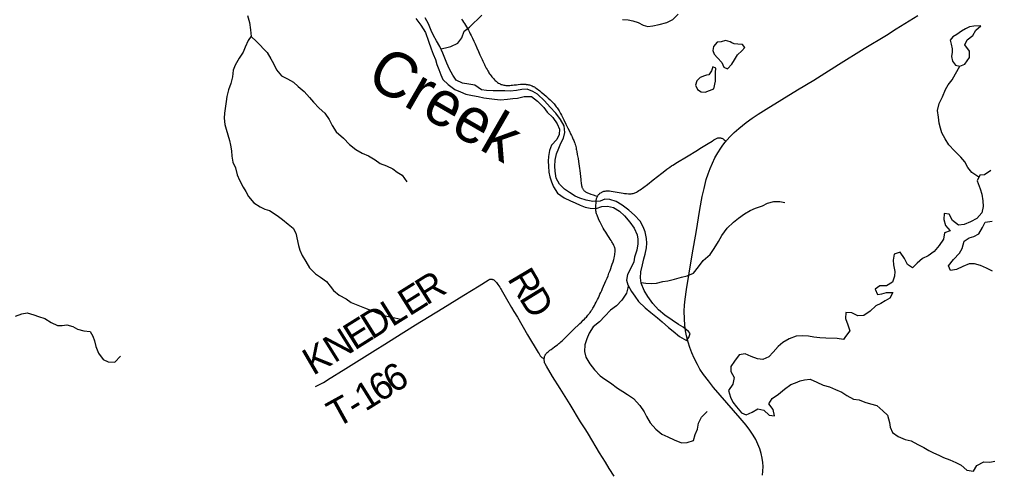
# Model space of a CAD drawing. Extents: x 1442749 to 1756758, y 235267 to 677782.
# Drawn here: x 1557967 to 1568709, y 507542 to 512566 of the extents above; entities that cross this region are included whole.
import ezdxf

# ---------------------------------------------------------------- set-up
doc = ezdxf.new("R2010")
doc.units = 0
for name, color, linetype in [('GM_X_Major_Lake', 7, 'Continuous'), ('GM_X_Major_River', 7, 'Continuous'), ('GM_X_Major_River_Text', 7, 'Continuous'), ('GM_X_Minor_Lake', 7, 'Continuous'), ('GM_X_Minor_River', 7, 'Continuous'), ('GM_X_State_Route', 7, 'Continuous'), ('GM_X_Township_Road', 7, 'Continuous'), ('GM_X_Township_Road_Text', 7, 'Continuous')]:
    doc.layers.add(name, color=color, linetype=linetype)

msp = doc.modelspace()

# ---------------------------------------------------------------- linework, layer by layer
at = {"layer": 'GM_X_Major_Lake'}
for points in [[(1568713, 510894), (1568643, 510848), (1568591, 510845), (1568560, 510782), (1568595, 510693), (1568613, 510634), (1568623, 510558), (1568629, 510495), (1568613, 510426), (1568556, 510365), (1568489, 510329), (1568418, 510299), (1568355, 510289), (1568287, 510343), (1568253, 510412), (1568195, 510419), (1568193, 510353), (1568211, 510287), (1568264, 510229)], [(1568729, 509782), (1568666, 509813), (1568599, 509843), (1568533, 509861), (1568471, 509863), (1568402, 509833), (1568331, 509801), (1568267, 509788), (1568245, 509841), (1568301, 509910), (1568365, 509982), (1568396, 510033), (1568418, 510113), (1568471, 510151), (1568526, 510166), (1568579, 510196), (1568621, 510263), (1568648, 510325), (1568727, 510336)], [(1568264, 510229), (1568201, 510205), (1568187, 510137), (1568141, 510066), (1568085, 510000), (1568020, 509951), (1567957, 509923), (1567899, 509871), (1567846, 509818), (1567789, 509854), (1567757, 509921), (1567711, 509990), (1567644, 509970), (1567632, 509902), (1567635, 509850), (1567649, 509779), (1567647, 509725), (1567623, 509658), (1567558, 509620), (1567486, 509618), (1567433, 509581), (1567457, 509524), (1567508, 509531), (1567558, 509544), (1567628, 509546), (1567596, 509484), (1567545, 509452), (1567495, 509423), (1567440, 509397), (1567376, 509340), (1567309, 509292), (1567241, 509286), (1567174, 509320), (1567110, 509324), (1567106, 509258), (1567130, 509189), (1567152, 509122), (1567104, 509057)], [(1567104, 509057), (1567081, 509024), (1567014, 509038), (1566888, 509041), (1566820, 509045), (1566754, 509051), (1566694, 509063), (1566632, 509066), (1566558, 509064), (1566483, 509034), (1566412, 508994), (1566359, 508948), (1566303, 508885), (1566258, 508834), (1566191, 508806), (1566131, 508812), (1566062, 508838), (1565995, 508868), (1565930, 508856), (1565876, 508787), (1565835, 508728), (1565837, 508672), (1565873, 508605), (1565857, 508531), (1565811, 508460), (1565831, 508386), (1565859, 508333), (1565898, 508282), (1565954, 508216), (1566007, 508194), (1566072, 508223), (1566135, 508257), (1566203, 508243), (1566259, 508187), (1566319, 508182), (1566303, 508250), (1566255, 508314), (1566292, 508373), (1566364, 508421), (1566429, 508475), (1566499, 508529), (1566551, 508548), (1566602, 508568), (1566652, 508581), (1566715, 508585), (1566786, 508553), (1566857, 508519), (1566926, 508503), (1566993, 508472), (1567064, 508442), (1567121, 508406), (1567192, 508366), (1567256, 508358), (1567317, 508332), (1567383, 508313), (1567450, 508295), (1567517, 508235), (1567569, 508187), (1567591, 508108), (1567599, 508056), (1567624, 507995), (1567688, 507954), (1567765, 507919), (1567831, 507903), (1567904, 507863), (1567971, 507830), (1568026, 507798), (1568079, 507772), (1568137, 507745), (1568188, 507719), (1568259, 507693), (1568324, 507665), (1568385, 507636), (1568448, 507580), (1568519, 507568), (1568559, 507633), (1568634, 507671), (1568702, 507669), (1568755, 507680)]]:
    msp.add_lwpolyline(points, dxfattribs=at)
at = {"layer": 'GM_X_Major_River'}
for points in [[(1562353, 512578), (1562409, 512504), (1562458, 512423), (1562491, 512326), (1562521, 512241), (1562543, 512182), (1562568, 512123), (1562586, 512069), (1562607, 512014), (1562627, 511953), (1562651, 511901), (1562708, 511845), (1562784, 511791), (1562845, 511765), (1562905, 511741), (1562980, 511725), (1563040, 511712), (1563103, 511698), (1563163, 511692), (1563221, 511683), (1563289, 511677), (1563365, 511683), (1563425, 511691), (1563477, 511696), (1563550, 511714), (1563632, 511715), (1563699, 511663), (1563767, 511593), (1563803, 511542), (1563869, 511480), (1563917, 511413), (1563940, 511354), (1563936, 511292), (1563910, 511239), (1563853, 511174), (1563829, 511117), (1563819, 511049), (1563817, 510997)], [(1563464, 511780), (1563396, 511774), (1563336, 511778), (1563266, 511778), (1563206, 511775), (1563132, 511779), (1563078, 511789), (1563004, 511839), (1562940, 511849), (1562870, 511861), (1562797, 511895), (1562761, 511950), (1562723, 512015), (1562695, 512084), (1562674, 512136), (1562652, 512193), (1562616, 512266), (1562580, 512331), (1562549, 512388), (1562523, 512445), (1562493, 512516), (1562455, 512583)], [(1565368, 509115), (1565309, 509161), (1565258, 509193), (1565187, 509241), (1565107, 509295), (1565038, 509353), (1564974, 509425), (1564919, 509500), (1564879, 509568), (1564845, 509647), (1564837, 509709), (1564842, 509773), (1564859, 509851), (1564875, 509918), (1564888, 509970), (1564902, 510038), (1564908, 510090), (1564903, 510144), (1564887, 510218), (1564865, 510271), (1564835, 510336), (1564770, 510402), (1564708, 510458), (1564636, 510510), (1564567, 510552), (1564497, 510574), (1564441, 510577), (1564391, 510557), (1564309, 510551), (1564237, 510567), (1564166, 510589), (1564114, 510612), (1564052, 510652), (1563997, 510690), (1563940, 510745), (1563904, 510810), (1563892, 510887), (1563888, 510943), (1563892, 511011), (1563908, 511081), (1563932, 511142), (1563957, 511196), (1563985, 511251), (1563999, 511315), (1563991, 511389), (1563951, 511458), (1563899, 511530), (1563839, 511597), (1563775, 511667), (1563699, 511738), (1563648, 511769), (1563582, 511795), (1563526, 511790), (1563464, 511780)], [(1563817, 510997), (1563818, 510943), (1563824, 510877), (1563835, 510824), (1563851, 510770), (1563875, 510713), (1563919, 510644), (1563994, 510592), (1564061, 510558), (1564114, 510536), (1564170, 510513), (1564225, 510491), (1564279, 510478), (1564345, 510476), (1564409, 510498), (1564473, 510502), (1564537, 510484), (1564604, 510445), (1564660, 510393), (1564718, 510323), (1564766, 510256), (1564800, 510185), (1564809, 510134), (1564809, 510082), (1564795, 510013), (1564771, 509937), (1564764, 509883), (1564725, 509808), (1564692, 509745), (1564684, 509681), (1564698, 509629), (1564738, 509557), (1564775, 509504), (1564815, 509445), (1564889, 509375), (1564952, 509325), (1565024, 509265), (1565075, 509220), (1565145, 509158), (1565200, 509118), (1565270, 509058), (1565345, 509016)], [(1565345, 509016), (1565370, 509048), (1565387, 509093), (1565368, 509115)]]:
    msp.add_lwpolyline(points, dxfattribs=at)
at = {"layer": 'GM_X_Minor_Lake'}
for points in [[(1568523, 512490), (1568475, 512483), (1568431, 512462), (1568386, 512436), (1568336, 512401), (1568293, 512372), (1568264, 512337), (1568275, 512294), (1568286, 512242), (1568286, 512204), (1568279, 512158), (1568290, 512106), (1568323, 512059), (1568368, 512050)], [(1568368, 512050), (1568423, 512073), (1568476, 512144), (1568476, 512214), (1568425, 512287), (1568452, 512341), (1568515, 512390), (1568547, 512449), (1568600, 512494), (1568523, 512490)], [(1565847, 512309), (1565829, 512317), (1565778, 512332), (1565729, 512319), (1565685, 512313), (1565644, 512268), (1565638, 512224), (1565651, 512182), (1565688, 512143)], [(1565688, 512143), (1565735, 512088), (1565760, 512040), (1565801, 512021), (1565846, 512072), (1565877, 512119), (1565911, 512173), (1565957, 512220), (1565990, 512257), (1565965, 512290), (1565915, 512291), (1565873, 512298), (1565847, 512309)], [(1565647, 511800), (1565665, 511883), (1565667, 511979), (1565671, 512027), (1565638, 512042), (1565623, 511996), (1565594, 511955), (1565566, 511948)], [(1565566, 511948), (1565546, 511944), (1565497, 511925), (1565461, 511887), (1565444, 511839), (1565467, 511791), (1565508, 511766), (1565554, 511763), (1565647, 511800)]]:
    msp.add_lwpolyline(points, dxfattribs=at)
at = {"layer": 'GM_X_Minor_River'}
for points in [[(1564638, 512567), (1564702, 512563), (1564754, 512552), (1564810, 512533), (1564865, 512502), (1564917, 512487), (1564975, 512496), (1565045, 512512), (1565128, 512533), (1565194, 512564), (1565254, 512624)], [(1560491, 512608), (1560513, 512532), (1560525, 512453), (1560532, 512377), (1560591, 512322), (1560706, 512201), (1560749, 512130), (1560778, 512078), (1560812, 512009), (1560867, 511942), (1560934, 511908), (1561000, 511871), (1561051, 511826), (1561116, 511770), (1561174, 511703), (1561219, 511652), (1561284, 511585), (1561345, 511530), (1561395, 511461), (1561428, 511394), (1561470, 511323), (1561553, 511251), (1561618, 511184), (1561688, 511126), (1561758, 511087), (1561829, 511059), (1561904, 511012), (1561959, 510973), (1562029, 510945), (1562096, 510912), (1562147, 510877), (1562201, 510842), (1562251, 510771)], [(1562628, 512241), (1562682, 512253), (1562740, 512265), (1562815, 512302), (1562860, 512361), (1562887, 512435), (1562944, 512482), (1563081, 512613)], [(1560532, 512381), (1560497, 512332), (1560463, 512260), (1560442, 512204), (1560399, 512137), (1560355, 512060), (1560330, 512006), (1560325, 511932), (1560307, 511857), (1560280, 511787), (1560262, 511715), (1560253, 511657), (1560236, 511531), (1560233, 511475), (1560240, 511405), (1560255, 511353), (1560274, 511290), (1560290, 511226), (1560301, 511176), (1560312, 511111), (1560317, 511055), (1560329, 510989), (1560356, 510924), (1560376, 510848), (1560403, 510787), (1560442, 510712), (1560471, 510661), (1560502, 510609), (1560560, 510537), (1560631, 510492), (1560683, 510467), (1560734, 510454), (1560817, 510396), (1560876, 510353), (1560941, 510302), (1560994, 510258), (1561023, 510202), (1561053, 510065), (1561069, 510015), (1561096, 509954), (1561137, 509889), (1561174, 509820), (1561242, 509751), (1561297, 509716), (1561364, 509668), (1561405, 509617), (1561440, 509567), (1561503, 509517), (1561582, 509474), (1561638, 509436), (1561709, 509405), (1561784, 509376), (1561852, 509350), (1561919, 509321), (1561997, 509291), (1562100, 509269), (1562172, 509254)], [(1568580, 510823), (1568502, 510874), (1568457, 510927), (1568423, 510991), (1568380, 511044), (1568311, 511112), (1568248, 511179), (1568208, 511246), (1568171, 511313), (1568154, 511365), (1568141, 511420), (1568133, 511486), (1568124, 511560), (1568142, 511636), (1568177, 511711), (1568211, 511791), (1568242, 511844), (1568285, 511897), (1568323, 511965), (1568368, 512050)], [(1564844, 509656), (1564895, 509647), (1564964, 509645), (1565015, 509650), (1565085, 509667), (1565139, 509676), (1565213, 509693), (1565292, 509715), (1565354, 509730), (1565425, 509759), (1565478, 509830), (1565530, 509899), (1565607, 509967), (1565653, 510034), (1565700, 510110), (1565738, 510177), (1565797, 510258), (1565865, 510325), (1565921, 510368), (1565986, 510414), (1566049, 510453), (1566108, 510480), (1566188, 510505), (1566243, 510534), (1566311, 510552), (1566379, 510551), (1566433, 510542)], [(1564702, 509621), (1564697, 509596), (1564684, 509537), (1564631, 509462), (1564573, 509397), (1564506, 509350), (1564443, 509285), (1564382, 509222), (1564315, 509165), (1564269, 509096), (1564242, 509033), (1564222, 508965), (1564219, 508893), (1564232, 508829), (1564278, 508756), (1564327, 508690), (1564391, 508625), (1564443, 508588), (1564506, 508545), (1564583, 508487), (1564640, 508450), (1564693, 508417), (1564758, 508373), (1564829, 508296), (1564879, 508227), (1564904, 508172), (1564945, 508105), (1565007, 508032), (1565072, 507977), (1565140, 507947), (1565211, 507914), (1565292, 507884), (1565354, 507887), (1565423, 507910), (1565442, 507975), (1565467, 508033), (1565479, 508099), (1565512, 508168), (1565576, 508229)], [(1557922, 509283), (1557993, 509310), (1558053, 509321), (1558126, 509299), (1558180, 509280), (1558248, 509257), (1558319, 509213), (1558388, 509182), (1558440, 509179), (1558492, 509186), (1558558, 509169), (1558611, 509139), (1558681, 509120), (1558749, 509115), (1558780, 509064), (1558797, 509012), (1558811, 508947), (1558842, 508873), (1558892, 508803), (1558948, 508778), (1559024, 508775), (1559085, 508842)]]:
    msp.add_lwpolyline(points, dxfattribs=at)
at = {"layer": 'GM_X_State_Route'}
msp.add_lwpolyline([(1566188, 507526), (1566192, 507569), (1566193, 507619), (1566190, 507665), (1566183, 507714), (1566172, 507766), (1566157, 507817), (1566136, 507869), (1566112, 507919), (1566084, 507968), (1566048, 508023), (1566006, 508079), (1565941, 508157), (1565645, 508495), (1565623, 508523), (1565588, 508567), (1565533, 508640), (1565495, 508697), (1565466, 508748), (1565430, 508818), (1565404, 508878), (1565393, 508907), (1565382, 508936), (1565364, 508995), (1565346, 509065), (1565335, 509123), (1565327, 509184), (1565323, 509253), (1565321, 509338), (1565324, 509406), (1565330, 509471), (1565345, 509578), (1565375, 509760), (1565414, 509986), (1565452, 510209), (1565494, 510465), (1565521, 510606), (1565540, 510696), (1565565, 510794), (1565584, 510857), (1565606, 510918), (1565632, 510978), (1565661, 511037), (1565692, 511091), (1565724, 511143), (1565747, 511176), (1565774, 511210), (1565783, 511221), (1565788, 511227), (1565795, 511234), (1565824, 511266), (1565872, 511315), (1565923, 511361), (1566005, 511427), (1566074, 511475), (1566140, 511518), (1566226, 511573), (1566572, 511786), (1566754, 511896), (1566835, 511947), (1567029, 512069), (1567311, 512243), (1567558, 512393), (1567666, 512461), (1567906, 512610)], dxfattribs=at)
at = {"layer": 'GM_X_Township_Road'}
for points in [[(1562857, 512569), (1562869, 512553), (1562880, 512537), (1562890, 512522), (1562901, 512504), (1562911, 512486), (1562923, 512465), (1562933, 512448), (1562944, 512427), (1562954, 512408), (1562964, 512387), (1562978, 512358), (1562993, 512327), (1563008, 512295), (1563027, 512252), (1563044, 512213), (1563060, 512176), (1563074, 512144), (1563084, 512124), (1563094, 512104), (1563103, 512083), (1563111, 512068), (1563117, 512055), (1563124, 512041), (1563131, 512028), (1563140, 512014), (1563148, 511999), (1563155, 511988), (1563161, 511977), (1563168, 511966), (1563175, 511956), (1563184, 511943), (1563194, 511930), (1563203, 511919), (1563213, 511908), (1563221, 511899), (1563229, 511891), (1563239, 511882), (1563248, 511875), (1563257, 511868), (1563267, 511862), (1563276, 511857), (1563286, 511852), (1563294, 511848), (1563304, 511845), (1563314, 511842), (1563325, 511839), (1563335, 511838), (1563346, 511836), (1563360, 511835), (1563373, 511836), (1563390, 511836), (1563407, 511838), (1563421, 511839), (1563441, 511841), (1563464, 511844), (1563485, 511847), (1563508, 511849), (1563524, 511850), (1563539, 511850), (1563548, 511850), (1563557, 511850), (1563567, 511849), (1563574, 511848), (1563582, 511847), (1563591, 511845), (1563600, 511844), (1563610, 511841), (1563619, 511838), (1563629, 511835), (1563637, 511831), (1563649, 511826), (1563655, 511823), (1563663, 511819), (1563672, 511814), (1563684, 511806), (1563698, 511796), (1563710, 511787), (1563722, 511778), (1563739, 511763), (1563753, 511752), (1563769, 511738), (1563798, 511712), (1563817, 511694), (1563838, 511675), (1563852, 511662), (1563862, 511652), (1563874, 511640), (1563882, 511631), (1563890, 511621), (1563898, 511612), (1563906, 511601), (1563915, 511589), (1563923, 511577), (1563930, 511566), (1563937, 511555), (1563944, 511542), (1563952, 511527), (1563962, 511509), (1563971, 511491), (1563989, 511454), (1564013, 511406), (1564034, 511364), (1564050, 511331), (1564064, 511301), (1564073, 511283), (1564080, 511269), (1564085, 511258), (1564090, 511247), (1564094, 511238), (1564098, 511228), (1564102, 511217), (1564107, 511205), (1564110, 511196), (1564113, 511184), (1564117, 511174), (1564120, 511160), (1564124, 511146), (1564127, 511132), (1564130, 511120), (1564133, 511104), (1564138, 511072), (1564146, 511026), (1564152, 510994), (1564156, 510968), (1564160, 510943), (1564164, 510917), (1564167, 510894), (1564170, 510861), (1564173, 510829), (1564176, 510796), (1564178, 510776), (1564179, 510762), (1564181, 510749), (1564183, 510739), (1564185, 510728), (1564187, 510718), (1564190, 510710), (1564192, 510703), (1564195, 510698), (1564198, 510692), (1564202, 510686), (1564207, 510680), (1564211, 510675), (1564215, 510670), (1564222, 510666), (1564230, 510660), (1564237, 510656), (1564244, 510652), (1564252, 510648), (1564262, 510644), (1564287, 510634), (1564314, 510625), (1564344, 510615), (1564361, 510609)], [(1564361, 510609), (1564366, 510616), (1564370, 510622), (1564374, 510628), (1564379, 510633), (1564384, 510638), (1564389, 510643), (1564397, 510649), (1564404, 510653), (1564411, 510657), (1564418, 510660), (1564425, 510663), (1564431, 510665), (1564438, 510666), (1564448, 510668), (1564458, 510669), (1564468, 510670), (1564479, 510670), (1564494, 510669), (1564513, 510667), (1564601, 510652), (1564644, 510645), (1564660, 510642), (1564684, 510639), (1564704, 510637), (1564716, 510636), (1564724, 510636), (1564733, 510637), (1564745, 510639), (1564755, 510642), (1564766, 510645), (1564774, 510648), (1564785, 510652), (1564793, 510657), (1564805, 510664), (1564819, 510672), (1564832, 510680), (1564848, 510691), (1564861, 510700), (1564875, 510710), (1564915, 510741), (1564977, 510790), (1565024, 510827), (1565074, 510867), (1565106, 510891), (1565128, 510908), (1565149, 510923), (1565163, 510933), (1565181, 510945), (1565195, 510954), (1565212, 510965), (1565229, 510975), (1565363, 511056), (1565448, 511109), (1565513, 511149), (1565586, 511194), (1565630, 511221), (1565649, 511234), (1565662, 511241), (1565671, 511246), (1565679, 511250), (1565685, 511252), (1565693, 511255), (1565700, 511256), (1565708, 511257), (1565713, 511257), (1565718, 511257), (1565723, 511256), (1565730, 511254), (1565736, 511252), (1565744, 511249), (1565750, 511246), (1565756, 511242), (1565764, 511236), (1565774, 511228), (1565783, 511221)], [(1563772, 508814), (1563774, 508826), (1563774, 508831), (1563776, 508838), (1563778, 508844), (1563781, 508850), (1563784, 508856), (1563787, 508860), (1563790, 508865), (1563794, 508869), (1563799, 508875), (1563805, 508881), (1563814, 508889), (1563823, 508897), (1563834, 508906), (1563848, 508916), (1563866, 508929), (1563886, 508943), (1563901, 508954), (1563920, 508968), (1563935, 508980), (1563946, 508989), (1563957, 508998), (1563969, 509009), (1563983, 509022), (1563997, 509035), (1564012, 509050), (1564031, 509068), (1564057, 509096), (1564111, 509150), (1564147, 509185), (1564166, 509202), (1564183, 509219), (1564203, 509238), (1564218, 509252), (1564230, 509264), (1564238, 509273), (1564246, 509283), (1564256, 509294), (1564264, 509304), (1564271, 509313), (1564280, 509326), (1564286, 509334), (1564293, 509345), (1564301, 509358), (1564309, 509371), (1564317, 509384), (1564327, 509403), (1564337, 509421), (1564346, 509438), (1564360, 509467), (1564371, 509488), (1564379, 509506), (1564389, 509527), (1564399, 509547), (1564408, 509568), (1564418, 509590), (1564429, 509616), (1564444, 509650), (1564455, 509676), (1564467, 509705), (1564478, 509731), (1564488, 509758), (1564500, 509790), (1564508, 509812), (1564517, 509837), (1564525, 509860), (1564534, 509886), (1564541, 509910), (1564546, 509927), (1564551, 509949), (1564554, 509962), (1564555, 509974), (1564557, 509997), (1564558, 510010), (1564557, 510019), (1564557, 510027), (1564555, 510035), (1564553, 510041), (1564550, 510050), (1564546, 510059), (1564542, 510067), (1564537, 510077), (1564532, 510086), (1564527, 510095), (1564520, 510106), (1564511, 510122), (1564501, 510136), (1564489, 510155), (1564476, 510176), (1564452, 510214), (1564437, 510238), (1564425, 510258), (1564414, 510278), (1564402, 510301), (1564390, 510324), (1564378, 510349), (1564368, 510371), (1564360, 510389), (1564356, 510402), (1564351, 510416), (1564347, 510428), (1564345, 510438), (1564343, 510449), (1564342, 510462), (1564342, 510475), (1564342, 510490), (1564343, 510505), (1564345, 510541), (1564347, 510556), (1564348, 510569), (1564350, 510579), (1564352, 510587), (1564354, 510593), (1564357, 510601), (1564361, 510609)], [(1561244, 508507), (1561300, 508534), (1561317, 508543), (1561331, 508551), (1561349, 508561), (1561376, 508578), (1561577, 508703), (1561814, 508852), (1561903, 508908), (1562008, 508974), (1562120, 509043), (1562350, 509188), (1562649, 509372), (1562884, 509516), (1563052, 509618), (1563151, 509681), (1563157, 509685), (1563161, 509687), (1563166, 509689), (1563172, 509692), (1563179, 509693), (1563185, 509693), (1563190, 509693), (1563195, 509692), (1563200, 509690), (1563207, 509688), (1563213, 509684), (1563218, 509681), (1563225, 509676), (1563231, 509670), (1563237, 509663), (1563245, 509655), (1563252, 509645), (1563260, 509635), (1563269, 509621), (1563280, 509604), (1563288, 509591), (1563296, 509577), (1563355, 509477), (1563411, 509381), (1563437, 509336), (1563475, 509271), (1563588, 509078), (1563705, 508881), (1563715, 508866), (1563722, 508853), (1563728, 508845), (1563734, 508838), (1563740, 508832), (1563747, 508827), (1563754, 508822), (1563762, 508818), (1563772, 508814)], [(1564546, 507514), (1564492, 507599), (1564449, 507668), (1564385, 507772), (1564261, 507977), (1564232, 508025), (1564210, 508060), (1564175, 508115), (1564058, 508305), (1563948, 508484), (1563865, 508618), (1563797, 508730), (1563782, 508755), (1563778, 508763), (1563776, 508768), (1563775, 508772), (1563774, 508777), (1563774, 508785), (1563773, 508795), (1563772, 508804), (1563772, 508814)]]:
    msp.add_lwpolyline(points, dxfattribs=at)

# ---------------------------------------------------------------- texts
at = {"layer": 'GM_X_Major_River_Text'}
msp.add_text('Creek', height=500, rotation=330.0034, dxfattribs=at).set_placement((1561783, 511862))
at = {"layer": 'GM_X_Township_Road_Text'}
for s, rotation, p in [('R', 32.0367, (1562470, 509398)), ('R', 300.5986, (1563359, 509699)), ('E', 32.0365, (1562279, 509278)), ('D', 301.6225, (1563488, 509482)), ('L', 32.0404, (1562089, 509159)), ('D', 32.0349, (1561865, 509019)), ('E', 32.0404, (1561675, 508900)), ('N', 32.0198, (1561451, 508760)), ('K', 30.2387, (1561215, 508622)), ('6', 32.2668, (1562109, 508422)), ('6', 32.2136, (1561952, 508324)), ('1', 31.99, (1561794, 508225)), ('T', 28.9539, (1561478, 508043)), ('-', 31.5322, (1561687, 508159))]:
    msp.add_text(s, height=300, rotation=rotation, dxfattribs=at).set_placement(p)

doc.saveas('drawing.dxf')
